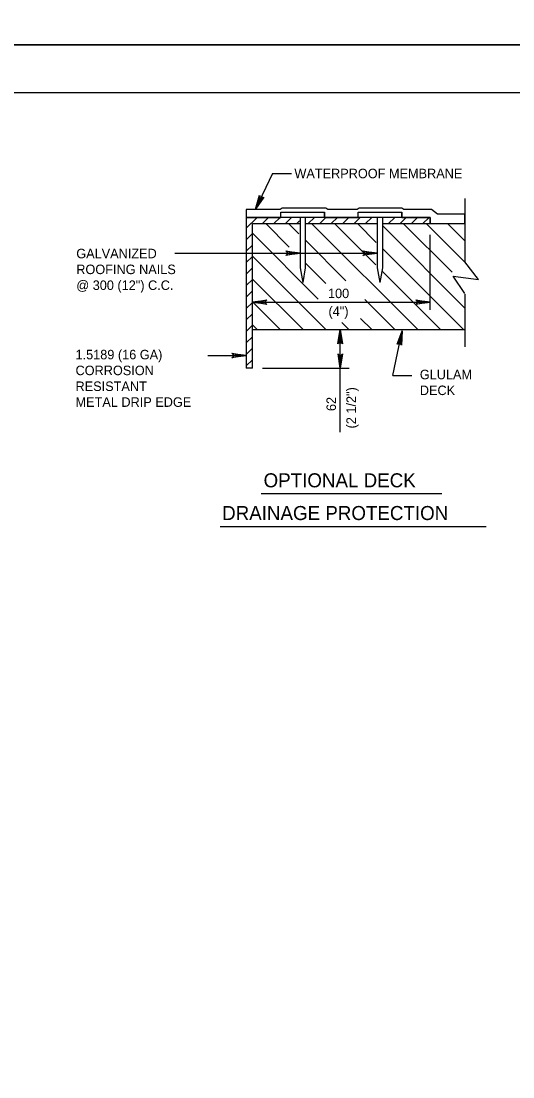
# Model space of a CAD drawing. Extents: x 638268 to 640277, y 295465 to 298435.
# Drawn here: x 638794.6 to 638949.9, y 296327.6 to 296661 of the extents above; entities that cross this region are included whole.
import ezdxf

# ---------------------------------------------------------------- set-up
doc = ezdxf.new("R2010")
doc.units = 0
for name, color, linetype in [('1', 7, 'Continuous'), ('2', 7, 'Continuous'), ('3', 7, 'Continuous'), ('4', 7, 'Continuous'), ('PLT-BNDY', 7, 'Continuous')]:
    doc.layers.add(name, color=color, linetype=linetype)

msp = doc.modelspace()

# ---------------------------------------------------------------- linework, layer by layer
at = {"layer": '1'}
for p, q in [((638874, 296612.89), (638868.63, 296601.56)), ((638934.73, 296604.94), (638934.73, 296584.99)), ((638923.76, 296598.99), (638865.71, 296598.99)), ((638865.71, 296598.99), (638865.71, 296551.34)), ((638865.71, 296595.57), (638869.14, 296598.99)), ((638870.82, 296597.05), (638872.76, 296598.99)), ((638874.44, 296597.05), (638876.38, 296598.99)), ((638878.06, 296597.05), (638880, 296598.99)), ((638882.73, 296598.99), (638882.73, 296583.05)), ((638884.35, 296598.99), (638884.35, 296583.05)), ((638885.3, 296597.05), (638887.24, 296598.99)), ((638888.92, 296597.05), (638890.86, 296598.99)), ((638892.54, 296597.05), (638894.48, 296598.99)), ((638896.16, 296597.05), (638898.1, 296598.99)), ((638899.78, 296597.05), (638901.72, 296598.99)), ((638903.4, 296597.05), (638905.34, 296598.99)), ((638907.09, 296598.99), (638907.09, 296583.05)), ((638908.71, 296598.99), (638908.71, 296583.05)), ((638910.64, 296597.05), (638912.58, 296598.99)), ((638914.26, 296597.05), (638916.2, 296598.99)), ((638917.88, 296597.05), (638919.82, 296598.99)), ((638921.5, 296597.05), (638923.44, 296598.99)), ((638923.76, 296597.05), (638923.76, 296598.99)), ((638867.65, 296551.34), (638867.65, 296597.05)), ((638867.65, 296597.05), (638882.58, 296597.05)), ((638879.26, 296589.64), (638871.85, 296597.05)), ((638882.35, 296593.79), (638879.09, 296597.05)), ((638881.68, 296597.05), (638882.54, 296597.92)), ((638884.65, 296597.05), (638906.87, 296597.05)), ((638919.83, 296563.56), (638886.33, 296597.05)), ((638906.64, 296583.99), (638893.57, 296597.05)), ((638906.76, 296591.11), (638900.81, 296597.05)), ((638908.77, 296597.05), (638923.76, 296597.05)), ((638934.73, 296570.37), (638908.89, 296596.21)), ((638930.68, 296581.67), (638915.29, 296597.05)), ((638934.73, 296584.86), (638922.53, 296597.05)), ((638923.76, 296597.05), (638934.73, 296597.05)), ((638934.73, 296591.57), (638929.25, 296597.05)), ((638865.71, 296591.95), (638867.65, 296593.89)), ((638888.45, 296573.21), (638867.65, 296594.01)), ((638923.76, 296569.82), (638923.76, 296593.51)), ((638865.71, 296588.33), (638867.65, 296590.27)), ((638897.14, 296579), (638884.39, 296591.75)), ((638934.31, 296563.56), (638908.94, 296588.93)), ((638865.71, 296584.71), (638867.65, 296586.65)), ((638890.86, 296563.56), (638867.65, 296586.77)), ((638865.71, 296581.09), (638867.65, 296583.03)), ((638882.73, 296583.05), (638883.54, 296578.43)), ((638884.35, 296583.05), (638883.54, 296578.43)), ((638890.78, 296578.12), (638884.5, 296584.41)), ((638907.09, 296583.05), (638907.9, 296578.43)), ((638908.71, 296583.05), (638907.9, 296578.43)), ((638865.71, 296577.47), (638867.65, 296579.41)), ((638883.62, 296563.56), (638867.65, 296579.53)), ((638927.07, 296563.56), (638908.62, 296582)), ((638865.71, 296573.85), (638867.65, 296575.78)), ((638876.38, 296563.56), (638867.65, 296572.29)), ((638912.59, 296563.56), (638903.1, 296573.04)), ((638934.73, 296574.74), (638934.73, 296558.14)), ((638865.71, 296570.23), (638867.65, 296572.16)), ((638865.71, 296566.61), (638867.65, 296568.54)), ((638898.1, 296563.56), (638895.86, 296565.8)), ((638905.35, 296563.56), (638901.82, 296567.08)), ((638865.71, 296562.99), (638867.65, 296564.92)), ((638869.14, 296563.56), (638867.65, 296565.05)), ((638895.4, 296531.15), (638895.4, 296563.56)), ((638912.03, 296549.09), (638914.95, 296563.22)), ((638865.71, 296559.37), (638867.65, 296561.3)), ((638865.71, 296555.74), (638867.65, 296557.68)), ((638865.71, 296552.12), (638867.65, 296554.06)), ((638867.65, 296551.34), (638865.71, 296551.34))]:
    msp.add_line(p, q, dxfattribs=at)
for points in [[(638870.97, 296605.23), (638870.62, 296605.22), (638868.63, 296601.56), (638870.97, 296605.23), (638871.23, 296605.35), (638868.63, 296601.56), (638870.22, 296605.4), (638870.01, 296605.67), (638868.63, 296601.56), (638869.92, 296605.97), (638870.01, 296605.67)], [(638878.41, 296588.27), (638878.57, 296587.95), (638882.73, 296587.73), (638878.41, 296588.27), (638878.19, 296588.46), (638882.73, 296587.73), (638878.58, 296587.52), (638878.43, 296587.21), (638882.73, 296587.73), (638878.19, 296587.01), (638878.43, 296587.21)], [(638902.77, 296588.27), (638902.93, 296587.95), (638907.09, 296587.73), (638902.77, 296588.27), (638902.55, 296588.46), (638907.09, 296587.73), (638902.94, 296587.52), (638902.79, 296587.21), (638907.09, 296587.73), (638902.55, 296587.01), (638902.79, 296587.21)], [(638934.76, 296574.98), (638931.02, 296580.42), (638939.07, 296579.4), (638934.73, 296584.99)], [(638871.97, 296571.72), (638871.8, 296572.03), (638867.65, 296572.26), (638871.97, 296571.72), (638872.19, 296571.53), (638867.65, 296572.26), (638871.8, 296572.46), (638871.95, 296572.77), (638867.65, 296572.26), (638872.19, 296572.98), (638871.95, 296572.77)], [(638919.44, 296572.8), (638919.6, 296572.49), (638923.76, 296572.26), (638919.44, 296572.8), (638919.22, 296572.99), (638923.76, 296572.26), (638919.61, 296572.05), (638919.46, 296571.74), (638923.76, 296572.26), (638919.22, 296571.54), (638919.46, 296571.74)], [(638894.86, 296559.24), (638895.17, 296559.4), (638895.4, 296563.56), (638894.86, 296559.24), (638894.67, 296559.02), (638895.4, 296563.56), (638895.6, 296559.41), (638895.91, 296559.26), (638895.4, 296563.56), (638896.12, 296559.02), (638895.91, 296559.26)], [(638913.55, 296559.1), (638913.89, 296559.2), (638914.95, 296563.22), (638913.55, 296559.1), (638913.32, 296558.92), (638914.95, 296563.22), (638914.31, 296559.11), (638914.58, 296558.9), (638914.95, 296563.22), (638914.74, 296558.63), (638914.58, 296558.9)], [(638861.4, 296555.95), (638861.56, 296555.63), (638865.71, 296555.39), (638861.4, 296555.95), (638861.18, 296556.14), (638865.71, 296555.39), (638861.56, 296555.2), (638861.41, 296554.89), (638865.71, 296555.39), (638861.18, 296554.69), (638861.41, 296554.89)], [(638895.94, 296555.66), (638895.63, 296555.5), (638895.4, 296551.34), (638895.94, 296555.66), (638896.13, 296555.88), (638895.4, 296551.34), (638895.19, 296555.49), (638894.88, 296555.65), (638895.4, 296551.34), (638894.68, 296555.88), (638894.88, 296555.65)]]:
    msp.add_lwpolyline(points, dxfattribs=at)
msp.add_lwpolyline([(638865.71, 296598.99), (638876.64, 296598.99), (638876.64, 296600.62), (638890.44, 296600.62), (638890.44, 296598.99), (638901, 296598.99), (638901, 296600.62), (638914.8, 296600.62), (638914.8, 296598.99), (638923.76, 296598.99), (638923.76, 296597.05), (638934.73, 296597.05), (638934.73, 296600.01), (638926.1, 296600.01), (638924.15, 296601.43), (638915.41, 296601.43), (638914.78, 296601.89), (638901.38, 296601.89), (638900.75, 296601.43), (638891.48, 296601.43), (638890.85, 296601.89), (638877.03, 296601.89), (638876.4, 296601.43), (638865.71, 296601.43)], close=True, dxfattribs=at)
at = {"layer": '2'}
for p, q in [((638475.46, 296638.46), (639261.46, 296638.46)), ((638870.38, 296511.82), (638927.44, 296511.82)), ((638857.49, 296501.35), (638941.46, 296501.35))]:
    msp.add_line(p, q, dxfattribs=at)
at = {"layer": '3'}
for p, q in [((638874, 296612.89), (638879.99, 296612.89)), ((638876.64, 296600.62), (638890.44, 296600.62)), ((638876.64, 296598.99), (638876.64, 296600.62)), ((638890.44, 296598.99), (638890.44, 296600.62)), ((638901, 296600.62), (638914.8, 296600.62)), ((638901, 296598.99), (638901, 296600.62)), ((638914.8, 296598.99), (638914.8, 296600.62)), ((638843.15, 296587.73), (638907.09, 296587.73)), ((638867.65, 296572.26), (638923.76, 296572.26)), ((638867.65, 296563.56), (638934.73, 296563.56)), ((638853.6, 296555.39), (638865.71, 296555.39)), ((638870.85, 296551.34), (638898.19, 296551.34)), ((638912.03, 296549.09), (638918.01, 296549.09))]:
    msp.add_line(p, q, dxfattribs=at)
at = {"layer": 'PLT-BNDY'}
for points in [[(638435.46, 297247.46), (639276.46, 297247.46), (639276.46, 296653.46), (638435.46, 296653.46)], [(638435.46, 296653.46), (639276.46, 296653.46), (639276.46, 296059.46), (638435.46, 296059.46)]]:
    msp.add_lwpolyline(points, close=True, dxfattribs=at)

# ---------------------------------------------------------------- texts
at = {"layer": '4'}
for s, height, p in [('WATERPROOF MEMBRANE', 3, (638880.9, 296611.35)), ('GALVANIZED', 3, (638812.02, 296586.08)), ('ROOFING NAILS', 3, (638812.02, 296581.08)), ('@ 300 (12") C.C.', 3, (638812.02, 296576.08)), ('100', 3, (638891.51, 296573.5)), ('(4")', 3, (638891.67, 296567.86)), ('1.5189 (16 GA)', 3, (638811.78, 296554.18)), ('CORROSION', 3, (638811.78, 296549.18)), ('GLULAM', 3, (638920.51, 296547.89)), ('RESISTANT', 3, (638811.78, 296544.18)), ('DECK', 3, (638920.51, 296542.89)), ('METAL DRIP EDGE', 3, (638811.78, 296539.18)), ('OPTIONAL DECK', 4.4292, (638871.17, 296513.77)), ('DRAINAGE PROTECTION', 4.4292, (638858.08, 296503.44))]:
    msp.add_text(s, height=height, dxfattribs=at).set_placement(p)
for s, p in [('(2 1/2")', (638900.32, 296532.36)), ('62', (638894.03, 296537.84))]:
    msp.add_text(s, height=3, rotation=90, dxfattribs=at).set_placement(p)

doc.saveas('drawing.dxf')
